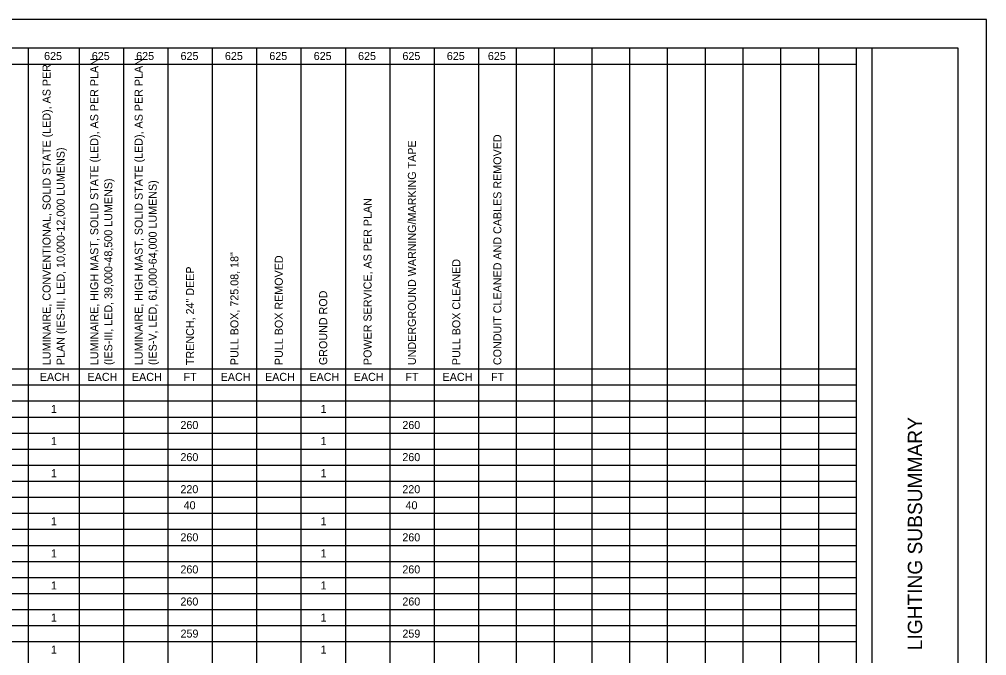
# Model space of a CAD drawing. Extents: x 0 to 34, y 0 to 22.
# Drawn here: x 17.13 to 34, y 10.89 to 22 of the extents above; entities that cross this region are included whole.
import ezdxf

# ---------------------------------------------------------------- set-up
doc = ezdxf.new("R2010")
doc.units = 0
for name, color, linetype in [('Default', 7, 'Continuous'), ('SH_Border', 7, 'Continuous'), ('SH_Cut_Line', 7, 'Continuous'), ('SH_Data', 7, 'Continuous')]:
    doc.layers.add(name, color=color, linetype=linetype)

msp = doc.modelspace()

# ---------------------------------------------------------------- linework, layer by layer
at = {"layer": 'Default'}
for p, q in [((1.5, 21.5), (31.724, 21.5)), ((17.279, 21.5), (17.279, 0.5)), ((18.168, 21.5), (18.168, 0.5)), ((18.942, 21.5), (18.942, 0.5)), ((19.716, 21.5), (19.716, 0.5)), ((20.491, 21.5), (20.491, 0.5)), ((21.265, 21.5), (21.265, 0.5)), ((22.039, 21.5), (22.039, 0.5)), ((22.813, 21.5), (22.813, 0.5)), ((23.587, 21.5), (23.587, 0.5)), ((24.361, 21.5), (24.361, 0.5)), ((25.135, 21.5), (25.135, 0.5)), ((25.794, 21.5), (25.794, 0.5)), ((26.453, 21.5), (26.453, 0.5)), ((27.112, 21.5), (27.112, 0.5)), ((27.771, 21.5), (27.771, 0.5)), ((28.429, 21.5), (28.429, 0.5)), ((29.088, 21.5), (29.088, 0.5)), ((29.747, 21.5), (29.747, 0.5)), ((30.406, 21.5), (30.406, 0.5)), ((31.065, 21.5), (31.065, 0.5)), ((31.724, 21.5), (31.724, 0.5)), ((8.451, 21.22), (31.724, 21.22)), ((8.451, 15.9), (31.724, 15.9)), ((1.5, 15.62), (31.724, 15.62)), ((1.5, 15.34), (31.724, 15.34)), ((1.5, 15.06), (31.724, 15.06)), ((1.5, 14.78), (31.724, 14.78)), ((1.5, 14.5), (31.724, 14.5)), ((1.5, 14.22), (31.724, 14.22)), ((1.5, 13.94), (31.724, 13.94)), ((1.5, 13.66), (31.724, 13.66)), ((1.5, 13.38), (31.724, 13.38)), ((1.5, 13.1), (31.724, 13.1)), ((1.5, 12.82), (31.724, 12.82)), ((1.5, 12.54), (31.724, 12.54)), ((1.5, 12.26), (31.724, 12.26)), ((1.5, 11.98), (31.724, 11.98)), ((1.5, 11.7), (31.724, 11.7)), ((1.5, 11.42), (31.724, 11.42)), ((1.5, 11.14), (31.724, 11.14))]:
    msp.add_line(p, q, dxfattribs=at)
at = {"layer": 'SH_Border'}
msp.add_line((32, 0.5), (32, 21.5), dxfattribs=at)
msp.add_lwpolyline([(1.5, 21.5), (33.5, 21.5), (33.5, 0.5), (1.5, 0.5)], close=True, dxfattribs=at)
at = {"layer": 'SH_Cut_Line'}
msp.add_lwpolyline([(0, 0), (34, 0), (34, 22), (0, 22)], close=True, dxfattribs=at)

# ---------------------------------------------------------------- texts
at = {"layer": 'Default'}
for s, p in [('625', (17.558, 21.29)), ('625', (18.39, 21.29)), ('625', (19.164, 21.29)), ('625', (19.938, 21.29)), ('625', (20.712, 21.29)), ('625', (21.487, 21.29)), ('625', (22.261, 21.29)), ('625', (23.035, 21.29)), ('625', (23.809, 21.29)), ('625', (24.583, 21.29)), ('625', (25.299, 21.29)), ('EACH', (17.484, 15.69)), ('EACH', (18.316, 15.69)), ('EACH', (19.09, 15.69)), ('FT', (19.991, 15.69)), ('EACH', (20.638, 15.69)), ('EACH', (21.412, 15.69)), ('EACH', (22.186, 15.69)), ('EACH', (22.96, 15.69)), ('FT', (23.862, 15.69)), ('EACH', (24.509, 15.69)), ('FT', (25.353, 15.69)), ('1', (17.678, 15.13)), ('1', (22.38, 15.13)), ('260', (19.936, 14.85)), ('260', (23.807, 14.85)), ('1', (17.678, 14.57)), ('1', (22.38, 14.57)), ('260', (19.936, 14.29)), ('260', (23.807, 14.29)), ('1', (17.678, 14.01)), ('1', (22.38, 14.01)), ('220', (19.936, 13.73)), ('220', (23.807, 13.73)), ('40', (19.992, 13.45)), ('40', (23.863, 13.45)), ('1', (17.678, 13.17)), ('1', (22.38, 13.17)), ('260', (19.936, 12.89)), ('260', (23.807, 12.89)), ('1', (17.678, 12.61)), ('1', (22.38, 12.61)), ('260', (19.936, 12.33)), ('260', (23.807, 12.33)), ('1', (17.678, 12.05)), ('1', (22.38, 12.05)), ('260', (19.936, 11.77)), ('260', (23.807, 11.77)), ('1', (17.678, 11.49)), ('1', (22.38, 11.49)), ('259', (19.938, 11.21)), ('259', (23.808, 11.21)), ('1', (17.678, 10.93)), ('1', (22.38, 10.93))]:
    msp.add_text(s, height=0.14, dxfattribs=at).set_placement(p)
for s, p in [('LUMINAIRE, HIGH MAST, SOLID STATE (LED), AS PER PLAN ', (18.503, 15.966)), ('LUMINAIRE, HIGH MAST, SOLID STATE (LED), AS PER PLAN ', (19.277, 15.966)), ('LUMINAIRE, CONVENTIONAL, SOLID STATE (LED), AS PER ', (17.671, 15.966)), ('CONDUIT CLEANED AND CABLES REMOVED', (25.535, 15.966)), ('PLAN (IES-III, LED, 10,000-12,000 LUMENS)', (17.916, 15.966)), ('UNDERGROUND WARNING/MARKING TAPE', (24.044, 15.966)), ('(IES-III, LED, 39,000-48,500 LUMENS)', (18.748, 15.966)), ('(IES-V, LED, 61,000-64,000 LUMENS)', (19.522, 15.966)), ('POWER SERVICE, AS PER PLAN', (23.27, 15.966)), ('PULL BOX, 725.08, 18"', (20.948, 15.966)), ('PULL BOX REMOVED', (21.722, 15.966)), ('PULL BOX CLEANED', (24.818, 15.966)), ('TRENCH, 24" DEEP', (20.174, 15.966)), ('GROUND ROD', (22.496, 15.966))]:
    msp.add_text(s, height=0.14, rotation=90, dxfattribs=at).set_placement(p)
at = {"layer": 'SH_Data'}
msp.add_text('LIGHTING SUBSUMMARY', height=0.25, rotation=90, dxfattribs=at).set_placement((32.875, 10.99))

doc.saveas('drawing.dxf')
